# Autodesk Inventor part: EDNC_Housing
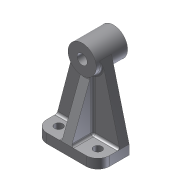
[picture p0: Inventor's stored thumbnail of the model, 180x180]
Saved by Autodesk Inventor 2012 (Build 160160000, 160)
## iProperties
Created: 2010-10
Part Number: EDNC_Housing
Document SubType Name: Modeling
Designer: JSSONG
Density: 1 g/cm^3
Mass: 136.139 g
Surface Area: 278.55 cm^2
Volume: 136.139 cm^3
Material: 기본값
Author: JSSONG
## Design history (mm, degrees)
sketch "스케치1"
  geometry: L1 (-18, 0)-(-40, -84); L2 (-40, -84)-(-40, -96); L3 (-40, -96)-(40, -96); L4 (40, -96)-(40, -84); L5 (40, -84)-(17.442, 4.448); L6 (-40, -84)-(40, -84); A1 r 18 centre (0, 0) between (-18, 0) and (17.442, 4.448); 2 further points
  constraints: 12 end point, 3 perpendicular, 2 point on circle, 1 centre point, 1 coincident, 1 midpoint, 1 parallel, 1 tangent, 1 vertical, 1 vertical alignment
  dimensions: "d0" = 36 diameter of A1; "d1" = 80 distance of L2.end L3.end; "d2" = 114 dimension on A1 L3; "d3" = 12 distance of L3.end L4.end
extrude "돌출1" new body sketch "스케치1" distance "d4" = 12; taper "d5" = 0 deg
extrude "돌출2" join sketch "스케치1" distance "d6" = 40; taper "d7" = 0 deg
extrude "돌출3" join sketch "스케치1" distance "d8" = 20; taper "d10" = 0 deg; dims "d9" = 20, "d11" = 0
sketch "스케치2"
  geometry: L1 (-84, 12)-(-84, 40) reference; L2 (-18, -20)-(-18, 20) reference; L3 (4.448, 12)-(-18, 12) reference; L4 (-10.08, 12)-(-84, 40); L5 (-84, 12)-(-10.08, 12); L6 (-74.485, 36.396)-(-25.898, 17.992); 3 further points
  constraints: 6 end point, 5 point on line, 1 collinear
  dimensions: "d12" = 5 distance of L2.end point (-18, 15)
feature "리브1" sketch "스케치2" dims "d17" = 1, "d18" = 12, "d19" = 0
fillet "모깎기1" dims "d15" = 15
fillet "모깎기2" dims "d16" = 3
fillet "모깎기3" dims "d20" = 3
fillet "모깎기4" dims "d21" = 3
hole "Hole1" diameter "d24" = 13; stored, may be unused: countersink angle "d28" = 90 deg, drill point angle "d30" = 118 deg; dims "d22" = 10, "d23" = 10, "d25" = 6, "d26" = 4, "d27" = 2, "d29" = 8
hole "Hole2" diameter "d33" = 10.5; stored, may be unused: countersink angle "d37" = 90 deg, drill point angle "d39" = 118 deg; dims "d31" = 10, "d32" = 10, "d34" = 6, "d35" = 4, "d36" = 2, "d38" = 8
node "솔리드1"
mirror "대칭1"
